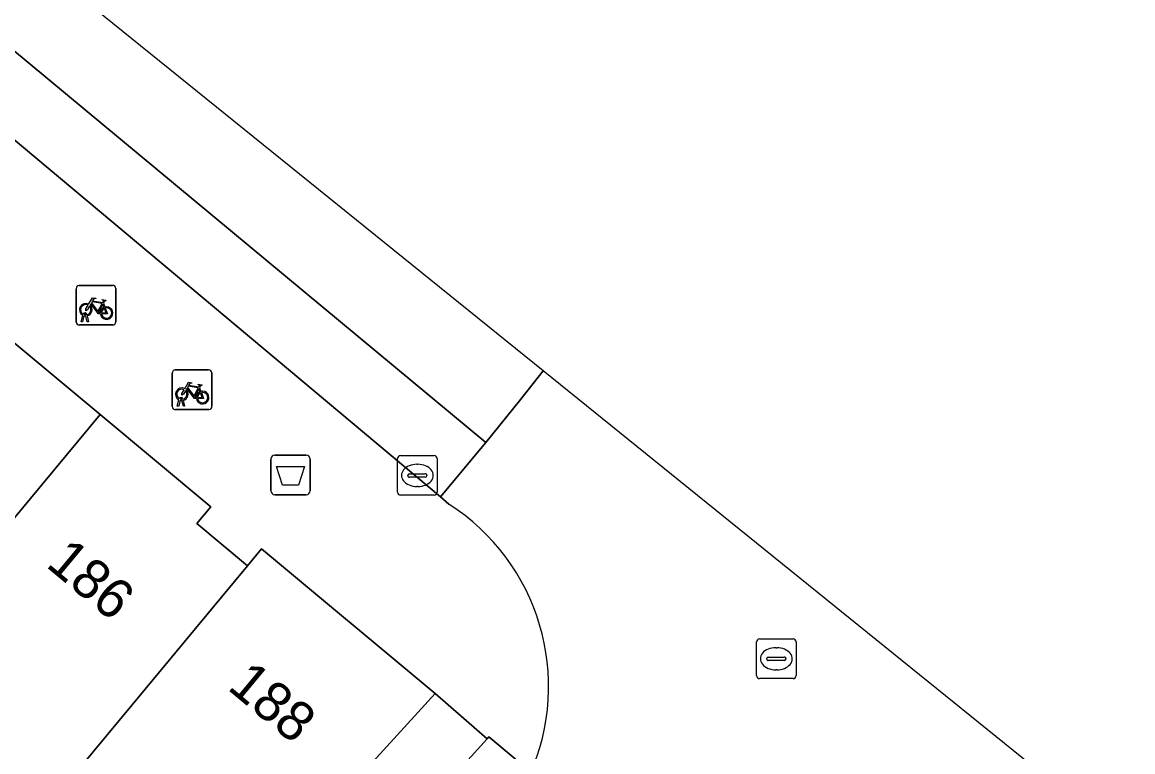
# Model space of a CAD drawing. Extents: x 161881 to 162523, y 381678 to 382381.
# Drawn here: x 162365 to 162393.04, y 381930.28 to 381948.7 of the extents above; entities that cross this region are included whole.
import ezdxf

# ---------------------------------------------------------------- set-up
doc = ezdxf.new("R2010")
doc.units = 0
for name, color, linetype in [('IMGEO_Afvalbak', 7, 'Continuous'), ('IMGEO_Fietsenrek', 7, 'Continuous'), ('IMGEO_Groenvoorziening', 7, 'Continuous'), ('IMGEO_Kolk', 7, 'Continuous'), ('IMGEO_Pand', 7, 'Continuous'), ('IMGEO_Pand_nummerreeks', 7, 'Continuous'), ('IMGEO_Rijbaan_lokaal_gesloten', 7, 'Continuous'), ('IMGEO_Rijbaan_lokaal_open', 7, 'Continuous'), ('IMGEO_Rioolput', 7, 'Continuous'), ('IMGEO_Voetpad_open', 7, 'Continuous')]:
    doc.layers.add(name, color=color, linetype=linetype)

msp = doc.modelspace()

# ---------------------------------------------------------------- linework, layer by layer
at = {"layer": 'IMGEO_Afvalbak'}
for p, q in [((162371.277, 381936.867), (162371.277, 381937.667)), ((162371.277, 381937.667), (162371.277, 381936.867)), ((162371.377, 381937.767), (162372.167, 381937.767)), ((162372.167, 381937.767), (162371.377, 381937.767)), ((162372.267, 381937.667), (162372.267, 381936.867)), ((162372.267, 381936.867), (162372.267, 381937.667)), ((162372.167, 381936.767), (162371.377, 381936.767)), ((162371.377, 381936.767), (162372.167, 381936.767))]:
    msp.add_line(p, q, dxfattribs=at)
msp.add_lwpolyline([(162371.42, 381937.481), (162372.124, 381937.481), (162371.975, 381937.011), (162371.569, 381937.011), (162371.42, 381937.481)], dxfattribs=at)
for centre, start, end in [((162371.377, 381937.667), 90, 180), ((162371.377, 381937.667), 90, 180), ((162372.167, 381937.667), 0, 90), ((162372.167, 381937.667), 360, 90), ((162371.377, 381936.867), 180, 270), ((162371.377, 381936.867), 180, 270), ((162372.167, 381936.867), 270, 0), ((162372.167, 381936.867), 270, 0)]:
    msp.add_arc(centre, 0.1, start, end, dxfattribs=at)
at = {"layer": 'IMGEO_Fietsenrek'}
for p, q in [((162366.436, 381942.053), (162367.277, 381942.053)), ((162367.277, 381942.053), (162366.436, 381942.053)), ((162366.361, 381941.128), (162366.361, 381941.969)), ((162366.361, 381941.969), (162366.361, 381941.128)), ((162367.361, 381941.978), (162367.361, 381941.137)), ((162367.361, 381941.137), (162367.361, 381941.978)), ((162367.048, 381941.602), (162367.084, 381941.507)), ((162366.488, 381941.137), (162366.527, 381941.297)), ((162366.557, 381941.285), (162366.522, 381941.137)), ((162366.599, 381941.309), (162366.598, 381941.313)), ((162366.64, 381941.137), (162366.606, 381941.279)), ((162366.63, 381941.32), (162366.631, 381941.313)), ((162366.638, 381941.283), (162366.673, 381941.137)), ((162367.286, 381941.053), (162366.445, 381941.053)), ((162366.445, 381941.053), (162367.286, 381941.053)), ((162366.522, 381941.137), (162366.488, 381941.137)), ((162366.673, 381941.137), (162366.64, 381941.137)), ((162368.787, 381938.994), (162368.787, 381939.835)), ((162368.787, 381939.835), (162368.787, 381938.994)), ((162368.862, 381939.919), (162369.703, 381939.919)), ((162369.703, 381939.919), (162368.862, 381939.919)), ((162369.787, 381939.844), (162369.787, 381939.003)), ((162369.787, 381939.003), (162369.787, 381939.844)), ((162369.474, 381939.468), (162369.51, 381939.373)), ((162368.914, 381939.003), (162368.953, 381939.163)), ((162368.948, 381939.003), (162368.914, 381939.003)), ((162368.983, 381939.151), (162368.948, 381939.003)), ((162369.025, 381939.175), (162369.024, 381939.179)), ((162369.066, 381939.003), (162369.032, 381939.145)), ((162369.056, 381939.186), (162369.057, 381939.179)), ((162369.064, 381939.149), (162369.099, 381939.003)), ((162369.099, 381939.003), (162369.066, 381939.003)), ((162369.712, 381938.919), (162368.871, 381938.919)), ((162368.871, 381938.919), (162369.712, 381938.919))]:
    msp.add_line(p, q, dxfattribs=at)
for points in [[(162366.674, 381941.579), (162366.769, 381941.743), (162366.855, 381941.729), (162366.857, 381941.72), (162366.801, 381941.709), (162366.774, 381941.664), (162367.03, 381941.623)], [(162366.695, 381941.527), (162366.643, 381941.437), (162366.603, 381941.412), (162366.604, 381941.459), (162366.659, 381941.553)], [(162366.97, 381941.335), (162366.92, 381941.335), (162366.729, 381941.586), (162366.71, 381941.554)], [(162367.017, 381941.598), (162366.76, 381941.639), (162366.743, 381941.61), (162366.91, 381941.39), (162367.017, 381941.598)], [(162367.065, 381941.5), (162367.035, 381941.577), (162366.926, 381941.359), (162366.969, 381941.359)], [(162366.999, 381941.359), (162367.119, 381941.358), (162367.075, 381941.472)], [(162367.095, 381941.479), (162367.15, 381941.334), (162367, 381941.334)], [(162367.03, 381941.623), (162367.055, 381941.672), (162367.049, 381941.676), (162367.026, 381941.68), (162367.014, 381941.687), (162367.013, 381941.69), (162367.015, 381941.695), (162367.11, 381941.68), (162367.112, 381941.67), (162367.102, 381941.657), (162367.09, 381941.651), (162367.076, 381941.657), (162367.048, 381941.602)], [(162369.1, 381939.445), (162369.195, 381939.609), (162369.281, 381939.595), (162369.283, 381939.586), (162369.227, 381939.575), (162369.2, 381939.53), (162369.456, 381939.489)], [(162369.443, 381939.464), (162369.186, 381939.505), (162369.169, 381939.476), (162369.336, 381939.256), (162369.443, 381939.464)], [(162369.456, 381939.489), (162369.481, 381939.538), (162369.475, 381939.542), (162369.452, 381939.546), (162369.44, 381939.553), (162369.439, 381939.556), (162369.441, 381939.561), (162369.536, 381939.546), (162369.538, 381939.536), (162369.528, 381939.523), (162369.516, 381939.517), (162369.502, 381939.523), (162369.474, 381939.468)], [(162369.121, 381939.393), (162369.069, 381939.303), (162369.029, 381939.278), (162369.03, 381939.325), (162369.085, 381939.419)], [(162369.396, 381939.201), (162369.346, 381939.201), (162369.155, 381939.452), (162369.136, 381939.42)], [(162369.491, 381939.366), (162369.461, 381939.443), (162369.352, 381939.225), (162369.395, 381939.225)], [(162369.425, 381939.225), (162369.545, 381939.224), (162369.501, 381939.338)], [(162369.521, 381939.345), (162369.576, 381939.2), (162369.426, 381939.2)]]:
    msp.add_lwpolyline(points, dxfattribs=at)
for centre, radius, start, end in [((162366.439, 381941.975), 0.0779, 92.4484, 184.2845), ((162366.439, 381941.975), 0.0779, 92.4484, 184.2845), ((162367.283, 381941.975), 0.0779, 2.4484, 94.2845), ((162367.283, 381941.975), 0.0779, 2.4484, 94.2845), ((162366.601, 381941.438), 0.159, 62.6766, 242.1369), ((162366.601, 381941.438), 0.129, 63.3192, 238.903), ((162366.601, 381941.438), 0.129, 283.6043, 43.4302), ((162366.601, 381941.438), 0.159, 283.5766, 46.6042), ((162367.128, 381941.354), 0.159, 113.3408, 178.3217), ((162367.128, 381941.354), 0.159, 187.0065, 105.7708), ((162367.128, 381941.354), 0.129, 113.923, 177.9556), ((162367.128, 381941.354), 0.129, 188.6715, 104.5883), ((162366.581, 381941.309), 0.0499, 12.8025, 158.6934), ((162366.601, 381941.438), 0.159, 253.9967, 271.7867), ((162366.581, 381941.309), 0.0174, 12.8025, 163.4502), ((162366.601, 381941.438), 0.129, 253.415, 269.0204), ((162366.439, 381941.131), 0.0779, 182.4484, 274.2845), ((162366.439, 381941.131), 0.0779, 182.4484, 274.2845), ((162367.283, 381941.131), 0.0779, 272.4484, 4.2845), ((162367.283, 381941.131), 0.0779, 272.4484, 4.2845), ((162368.865, 381939.841), 0.0779, 92.4484, 184.2845), ((162368.865, 381939.841), 0.0779, 92.4484, 184.2845), ((162369.709, 381939.841), 0.0779, 2.4484, 94.2845), ((162369.709, 381939.841), 0.0779, 2.4484, 94.2845), ((162369.027, 381939.304), 0.159, 62.6766, 242.1369), ((162369.027, 381939.304), 0.129, 63.3192, 238.903), ((162369.007, 381939.175), 0.0499, 12.8025, 158.6934), ((162369.027, 381939.304), 0.129, 283.6043, 43.4302), ((162369.027, 381939.304), 0.159, 283.5766, 46.6042), ((162369.554, 381939.22), 0.159, 113.3408, 178.3217), ((162369.554, 381939.22), 0.159, 187.0065, 105.7708), ((162369.554, 381939.22), 0.129, 113.923, 177.9556), ((162369.554, 381939.22), 0.129, 188.6715, 104.5883), ((162368.865, 381938.997), 0.0779, 182.4484, 274.2845), ((162368.865, 381938.997), 0.0779, 182.4484, 274.2845), ((162369.027, 381939.304), 0.159, 253.9967, 271.7867), ((162369.007, 381939.175), 0.0174, 12.8025, 163.4502), ((162369.027, 381939.304), 0.129, 253.415, 269.0204), ((162369.709, 381938.997), 0.0779, 272.4484, 4.2845), ((162369.709, 381938.997), 0.0779, 272.4484, 4.2845)]:
    msp.add_arc(centre, radius, start, end, dxfattribs=at)
at = {"layer": 'IMGEO_Groenvoorziening'}
msp.add_lwpolyline([(162377.462, 381929.977), (162377.495, 381930.057), (162376.782, 381930.65), (162376.741, 381930.606), (162374.965, 381928.638), (162375.845, 381927.879)], dxfattribs=at)
at = {"layer": 'IMGEO_Kolk'}
for p, q in [((162374.475, 381936.829), (162374.475, 381937.681)), ((162374.55, 381937.755), (162375.402, 381937.755)), ((162375.476, 381937.681), (162375.476, 381936.829)), ((162374.734, 381937.249), (162374.734, 381937.261)), ((162374.777, 381937.298), (162375.175, 381937.298)), ((162374.963, 381937.535), (162374.988, 381937.535)), ((162375.218, 381937.261), (162375.218, 381937.249)), ((162375.172, 381937.212), (162374.774, 381937.212)), ((162375.402, 381936.755), (162374.55, 381936.755)), ((162374.986, 381936.975), (162374.961, 381936.975))]:
    msp.add_line(p, q, dxfattribs=at)
for points in [[(162374.475, 381936.829), (162374.475, 381937.681)], [(162374.55, 381937.755), (162375.402, 381937.755)], [(162375.476, 381937.681), (162375.476, 381936.829)], [(162375.402, 381936.755), (162374.55, 381936.755)]]:
    msp.add_lwpolyline(points, dxfattribs=at)
for centre, radius, start, end in [((162374.552, 381937.679), 0.0765, 91.552, 178.448), ((162374.552, 381937.679), 0.0765, 91.552, 178.448), ((162375.4, 381937.679), 0.0765, 1.552, 88.448), ((162375.4, 381937.679), 0.0765, 1.552, 88.448), ((162374.774, 381937.258), 0.0403, 85.8775, 175.7526), ((162375.179, 381937.26), 0.0386, 1.7309, 96.639), ((162374.771, 381937.248), 0.0366, 178.938, 274.7102), ((162375.175, 381937.255), 0.043, 264.8664, 352.4533), ((162374.552, 381936.831), 0.0765, 181.552, 268.448), ((162374.552, 381936.831), 0.0765, 181.552, 268.448), ((162375.4, 381936.831), 0.0765, 271.552, 358.448), ((162375.4, 381936.831), 0.0765, 271.552, 358.448)]:
    msp.add_arc(centre, radius, start, end, dxfattribs=at)
for centre, major_axis, ratio, start_param, end_param in [((162374.962, 381937.255), (-0.387, 0.002), 0.722429, 4.712389, 7.853982), ((162374.987, 381937.255), (-0.39, 0.002), 0.717154, 1.570796, 4.712389)]:
    msp.add_ellipse(centre, major_axis=major_axis, ratio=ratio, start_param=start_param, end_param=end_param, dxfattribs=at)
at = {"layer": 'IMGEO_Pand'}
for points in [[(162366.966, 381938.791), (162363.876, 381941.359), (162363.534, 381940.948), (162362.555, 381941.762), (162357.039, 381935.118), (162361.108, 381931.735)], [(162370.688, 381934.975), (162369.409, 381936.038), (162369.763, 381936.465), (162366.966, 381938.791), (162361.108, 381931.735), (162365.186, 381928.345)], [(162375.427, 381931.75), (162371.039, 381935.397), (162370.688, 381934.975), (162365.186, 381928.345), (162365.401, 381928.166), (162369.246, 381924.97)]]:
    msp.add_lwpolyline(points, close=True, dxfattribs=at)
at = {"layer": 'IMGEO_Rijbaan_lokaal_gesloten'}
msp.add_lwpolyline([(162375.563, 381936.718), (162376.704, 381938.084), (162339.352, 381969.106), (162338.251, 381967.787), (162361.697, 381948.318), (162361.804, 381948.229)], close=True, dxfattribs=at)
at = {"layer": 'IMGEO_Rijbaan_lokaal_open'}
for points in [[(162338.096, 381967.916), (162338.251, 381967.787), (162339.352, 381969.106), (162376.704, 381938.084), (162377.551, 381939.142), (162378.151, 381939.893), (162347.686, 381964.494), (162343.107, 381969.212), (162336.093, 381975.038)], [(162393.04, 381927.87), (162378.151, 381939.893), (162377.551, 381939.142), (162376.704, 381938.084), (162375.563, 381936.718), (162375.768, 381936.531)]]:
    msp.add_lwpolyline(points, dxfattribs=at)
msp.add_arc((162372.822, 381931.927), 5.466, 335.7145, 57.383, dxfattribs=at)
at = {"layer": 'IMGEO_Rioolput'}
for p, q in [((162383.538, 381932.198), (162383.538, 381933.05)), ((162383.613, 381933.124), (162384.465, 381933.124)), ((162384.539, 381933.05), (162384.539, 381932.198)), ((162384.026, 381932.904), (162384.051, 381932.904)), ((162383.797, 381932.618), (162383.797, 381932.63)), ((162384.235, 381932.581), (162383.837, 381932.581)), ((162383.84, 381932.667), (162384.238, 381932.667)), ((162384.281, 381932.63), (162384.281, 381932.618)), ((162384.049, 381932.344), (162384.024, 381932.344)), ((162384.465, 381932.124), (162383.613, 381932.124))]:
    msp.add_line(p, q, dxfattribs=at)
for points in [[(162383.538, 381932.198), (162383.538, 381933.05)], [(162383.613, 381933.124), (162384.465, 381933.124)], [(162384.539, 381933.05), (162384.539, 381932.198)], [(162384.465, 381932.124), (162383.613, 381932.124)]]:
    msp.add_lwpolyline(points, dxfattribs=at)
for centre, radius, start, end in [((162383.615, 381933.048), 0.0765, 91.552, 178.448), ((162383.615, 381933.048), 0.0765, 91.552, 178.448), ((162384.463, 381933.048), 0.0765, 1.552, 88.448), ((162384.463, 381933.048), 0.0765, 1.552, 88.448), ((162383.837, 381932.627), 0.0403, 85.8775, 175.7526), ((162383.834, 381932.617), 0.0366, 178.938, 274.7102), ((162384.238, 381932.624), 0.043, 264.8664, 352.4533), ((162384.242, 381932.629), 0.0386, 1.7309, 96.639), ((162383.615, 381932.2), 0.0765, 181.552, 268.448), ((162383.615, 381932.2), 0.0765, 181.552, 268.448), ((162384.463, 381932.2), 0.0765, 271.552, 358.448), ((162384.463, 381932.2), 0.0765, 271.552, 358.448)]:
    msp.add_arc(centre, radius, start, end, dxfattribs=at)
for centre, major_axis, ratio, start_param, end_param in [((162384.025, 381932.624), (-0.387, 0.002), 0.722429, 4.712389, 7.853982), ((162384.05, 381932.624), (-0.39, 0.002), 0.717154, 1.570796, 4.712389)]:
    msp.add_ellipse(centre, major_axis=major_axis, ratio=ratio, start_param=start_param, end_param=end_param, dxfattribs=at)
at = {"layer": 'IMGEO_Voetpad_open'}
for points in [[(162375.768, 381936.531), (162375.563, 381936.718), (162361.804, 381948.229), (162361.697, 381948.318)], [(162363.876, 381941.359), (162366.966, 381938.791), (162369.763, 381936.465), (162369.409, 381936.038), (162370.688, 381934.975), (162371.039, 381935.397), (162375.427, 381931.75), (162376.741, 381930.606), (162376.782, 381930.65), (162377.495, 381930.057), (162377.462, 381929.977), (162377.804, 381929.679)], [(162374.804, 381928.776), (162374.965, 381928.638), (162376.741, 381930.606), (162375.427, 381931.75), (162369.246, 381924.97), (162366.613, 381922.037), (162365.423, 381920.73), (162365.317, 381920.614), (162367.769, 381918.348), (162368.155, 381918.773), (162368.347, 381918.986)]]:
    msp.add_lwpolyline(points, dxfattribs=at)
msp.add_arc((162372.822, 381931.927), 5.466, 335.7145, 57.383, dxfattribs=at)

# ---------------------------------------------------------------- texts
at = {"layer": 'IMGEO_Pand_nummerreeks'}
for s, rotation, p in [('186', 320.2081, (162365.567, 381934.971)), ('188', 320.2711, (162370.149, 381931.871))]:
    msp.add_text(s, height=1, rotation=rotation, dxfattribs=at).set_placement(p)

doc.saveas('drawing.dxf')
